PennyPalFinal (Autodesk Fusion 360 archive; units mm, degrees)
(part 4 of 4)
sketch "Sketch4" plane through (0, 0, 0) normal (0, 0, 1) x axis (1, 0, 0)
  line L1 (-27.9, 0) -> (-28, 0)
  line L2 (-27.8, -1.4) -> (-27.8, -0.1)
  line L3 (-28, -1.5) -> (-27.9, -1.5)
  line L4 (-28.1, -1.7) -> (-28.1, -1.6)
  line L5 (-27.9817, -1.8) -> (-28, -1.8)
  line L6 (-26.6181, -2.9407) -> (-27.6692, -1.9262)
  line L7 (-26.2684, -2.7223) -> (-26.4767, -2.9382)
  line L8 (-27.3, -0.9932) -> (-27.3, 0.4586)
  line L9 (-26.8722, -2.0005) -> (-26.2709, -2.5809)
  line L10 (-27.3, -1.5877) -> (-27.3, -1.5)
  line L11 (-29, 0) -> (-28, 0)
  line L12 (-29, 1.2) -> (-29, 0)
  line L13 (-28.0414, 1.2) -> (-29, 1.2)
  line L14 (-27.3293, 0.5293) -> (-27.9707, 1.1707)
  arc A1 centre (-26.5487, -2.8687) radius 0.1 clockwise from (-26.4767, -2.9382) to (-26.6181, -2.9407)
  arc A2 centre (-26.3403, -2.6528) radius 0.1 clockwise from (-26.2709, -2.5809) to (-26.2684, -2.7223)
  arc A3 centre (-28, -1.7) radius 0.1 clockwise from (-28, -1.8) to (-28.1, -1.7)
  arc A4 centre (-28, -1.6) radius 0.1 clockwise from (-28.1, -1.6) to (-28, -1.5)
  arc A5 centre (-27.9, -1.4) radius 0.1 clockwise from (-27.8, -1.4) to (-27.9, -1.5)
  arc A6 centre (-27.9, -0.1) radius 0.1 clockwise from (-27.9, 0) to (-27.8, -0.1)
  arc A7 centre (-28.0414, 1.1) radius 0.1 clockwise from (-28.0414, 1.2) to (-27.9707, 1.1707)
  arc A8 centre (-27.4, 0.4586) radius 0.1 clockwise from (-27.3293, 0.5293) to (-27.3, 0.4586)
  arc A9 centre (-25.9, -0.9932) radius 1.4 clockwise from (-26.8722, -2.0005) to (-27.3, -0.9932)
  arc A10 centre (-27.9817, -2.25) radius 0.45 clockwise from (-27.9817, -1.8) to (-27.6692, -1.9262)
  point P3 (-28, -1.5)
  point P18 (-28, -1.5)
  point P4 (-27.3, -1.5)
  point P5 (-27.3, -1.5877)
  horizontal L1
  perpendicular L1 L2
  perpendicular L2 L3
  perpendicular L4 L5
  perpendicular L6 L7
  perpendicular L7 L9
  parallel L8 L10
  parallel L1 L11
  perpendicular L11 L12
  perpendicular L12 L13
  tangent L6 A1
  tangent L7 A1
  tangent L7 A2
  tangent L9 A2
  equal A1 A2
  tangent L4 A3
  tangent L5 A3
  equal A1 A3
  tangent L4 A4
  equal A1 A4
  coincident P3 P18
  tangent L3 A5
  tangent L2 A5
  equal A1 A5
  tangent L1 A6
  tangent L2 A6
  equal A1 A6
  tangent L13 A7
  tangent L14 A7
  equal A1 A7
  tangent L14 A8
  tangent L8 A8
  equal A1 A8
  coincident P4 L8
  coincident L9 P5
  tangent L8 A9
  tangent L9 A9
  tangent L5 A10
  tangent L6 A10
  dimension "d62" radius A1 = 0.1
  dimension "d63" radius A9 = 1.4
  dimension "d64" radius A10 = 0.45
sweep "Sweep1" sketch "Sketch4" TwistAngle 0 TaperAngle 0
combine "Combine1"
extrude "Extrude14" new body sketch "Sketch3" profile of A4 L11 L12 A3 along normal blind 8
move "Move3"
combine "Combine2"
fillet "Fillet7" radius 9
component_from_bodies "Body->Comp1"
component_from_bodies "Body->Comp2"
extrude "Extrude2" add of existing geometry blind 4
extrude "Extrude3" cut of existing geometry blind -4
move "Move4"
extrude "Extrude4" add sketch "Sketch2" profile of C2 along normal blind 5
extrude "Extrude5" cut sketch "Sketch2" profile of C2 along normal blind 3
extrude "Extrude6" add of existing geometry blind 4
move "Move5"
extrude "Extrude16" new body sketch "Sketch3" profile of A4 L11 L12 A3 against normal blind 13
extrude "Extrude17" cut sketch "Sketch3" profile of A4 L11 L12 A3 against normal blind 5
move "Move6"
extrude "Extrude21" new body sketch "Sketch3" profile of C1 A7 L16 L17 A6 along normal blind 2
move "Move9"
component_from_bodies "Body->Comp3"
remove_body "RemoveBody4"
remove_body "RemoveBody5"
extrude "Extrude22" new body sketch "Sketch1" profile of C3 A4 L9 L8 A1 L7 L6 A3 A2 along normal blind 2
component_from_bodies "Body->Comp4"
sketch "Sketch5" plane through (0, 9, 0) normal (0, -1, 0) x axis (1, 0, 0)
  line L1 (-13.7255, 16.5488) -> (-11.1719, 13.4699)
  line L2 (0, 21.5) -> (0, 0)
  line L3 (13.7255, 16.5488) -> (11.1719, 13.4699)
  line L4 (-14.0447, 16.9336) -> (-13.7255, 16.5488)
  line L5 (14.0447, 16.9336) -> (13.7255, 16.5488)
  circle C1 centre (0, 0) radius 22
  circle C2 centre (0, 0) radius 17.5
  circle C3 centre (0, 0) radius 22
  point P1 (0, 0)
  point P2 (0, 0)
  point P3 (-13.7255, 16.5488)
  point P5 (13.7255, 16.5488)
  point P8 (0, 0)
  point P9 (-14.0447, 16.9336)
  point P10 (14.0447, 16.9336)
  coincident P1 P2
  vertical L2
  symmetric P3 L2 P5
  coincident P1 P8
  coincident C1 P9
  parallel L1 L4
  coincident C1 P10
  parallel L3 L5
  dimension "d125" diameter C1 = 44
extrude "Extrude9" cut sketch "Sketch1" profile of C2 C3 along normal blind 6
extrude "Extrude10" cut sketch "Sketch1" profile of C1 C2 along normal blind 16
extrude "Extrude12" cut sketch "Sketch5" profile of L1 L3 C1 L4 L5 C2 C3 against normal blind 8
extrude "Extrude1" cut sketch "Sketch3" profile of C3 C4 along normal blind 3
extrude "Extrude13" cut sketch "Sketch3" profile of C3 C4 along normal blind 8.78
scale "Scale1" ScaleFactor 1.01
fillet "Fillet1" radius 11
extrude "Extrude14" cut of existing geometry blind -3
fillet "Fillet3" radius 4.5
extrude "Extrude15" add of existing geometry blind 3
sketch "Sketch7" plane through (0, 12.22, 0) normal (0, -1, 0) x axis (1, 0, 0)
  line L1 (11.3086, 13.4396) -> (14.2101, 16.9379)
  line L2 (-14.1601, 16.9379) -> (-11.2586, 13.4396)
  arc A1 centre (0.025, -0.165) radius 17.675 clockwise from (11.3086, 13.4396) to (-11.2586, 13.4396)
  arc A2 centre (0.025, -0.165) radius 22.22 clockwise from (14.2101, 16.9379) to (-14.1601, 16.9379)
  circle C1 centre (0.025, -0.165) radius 19.5
  concentric A1 C1
  dimension "d166" diameter C1 = 39
extrude "Extrude21" cut sketch "Sketch7" profile of L1 A1 L2 C1 against normal blind 4
extrude "Extrude22" cut sketch "Sketch5" profile of L1 L3 C1 L4 L5 C2 C3 against normal blind 26
move "Move1"
sketch "Sketch6" plane through (0, -15.02, 0) normal (0, -1, 0) x axis (1, 0, 0)
  line L1 (-2.5, -16.94) -> (-7.55, -16.94)
  line L2 (-7.55, 16.61) -> (-2.5, 16.61)
  line L3 (-5.025, -0.165) -> (-5.025, 16.61)
  curve K1 (-7.675, -0.165) -> (-17.675, -0.165)
  curve K2 (-12.675, 10.835) -> (-12.675, -11.165)
  arc A1 centre (-7.55, -0.165) radius 16.775 clockwise from (-7.55, -16.94) to (-7.55, 16.61)
  arc A2 centre (-2.5, -0.165) radius 16.775 clockwise from (-2.5, 16.61) to (-2.5, -16.94)
  closed curve K3 centre (-12.675, -0.165)
  closed curve K4 centre (2.625, -0.165)
  point P8 (-5.025, 16.61)
  point P11 (-17.675, -0.165)
  point P12 (-7.675, -0.165)
  point P13 (-12.675, -11.165)
  point P14 (-12.675, 10.835)
  midpoint L2 P8
  coincident K3 P11
  coincident K3 P12
  coincident K3 P13
  coincident K3 P14
  symmetric L3 K3 K4
  dimension "d156" distance K3 = 10
  dimension "d157" = 22
extrude "Extrude1" cut sketch "Sketch6" profile of K3 K4 against normal blind 5
extrude "Extrude18" add of existing geometry blind 3
extrude "Extrude23" cut of existing geometry blind -3
extrude "Extrude24" cut of existing geometry blind -5
extrude "Extrude25" cut of existing geometry blind -4
extrude "Extrude23" add of existing geometry blind 6
fillet "Fillet8" radius 1.5
sketch "Sketch8" plane through (0, 23.37, 0) normal (0, 1, 0) x axis (-1, 0, 0)
  line L1 (2.5, -25.92) -> (7.55, -25.92)
  line L2 (7.55, 25.59) -> (2.5, 25.59)
  line L3 (2.5, 27.61) -> (7.55, 27.61)
  line L4 (7.55, -27.94) -> (2.5, -27.94)
  arc A1 centre (7.55, -0.165) radius 25.755 clockwise from (7.55, 25.59) to (7.55, -25.92)
  arc A2 centre (2.5, -0.165) radius 25.755 clockwise from (2.5, -25.92) to (2.5, 25.59)
  arc A3 centre (7.55, -0.165) radius 27.775 clockwise from (7.55, 27.61) to (7.55, -27.94)
  arc A4 centre (2.5, -0.165) radius 27.775 clockwise from (2.5, -27.94) to (2.5, 27.61)
extrude "Extrude20" cut of existing geometry blind -3
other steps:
base_feature "Base Feature1"
move "Move1"
base_feature "Base Feature1"
base_feature "Base Feature1" bodies "top"
scale "Scale1" ScaleFactor 1.01
move "Move1"
base_feature "Base Feature1" bodies "bottom"
scale "Scale1" ScaleFactor 1.01
move "Move1"
scale "Scale1" ScaleFactor 1.01
move "Move10"
create_component "CreateComponent1"
reparent_decal "ReparentDecal1"
remove_body "RemoveBody1"
create_component "CreateComponent2"
reparent_decal "ReparentDecal2"
remove_body "RemoveBody2"
create_component "CreateComponent4"
reparent_decal "ReparentDecal3"
remove_body "RemoveBody3"
create_component "CreateComponent5"
reparent_decal "ReparentDecal4"
remove_body "RemoveBody6"
named bodies: "speaker", "bottom", "top"

design "switch"
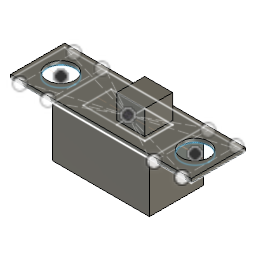
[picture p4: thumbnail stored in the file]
part number: 2026-06-04-23-07-11-302
sketch "Sketch1" plane through (0, 0, 0) normal (0, 0, 1) x axis (1, 0, 0)
  line L1 (-9.7, 2.9) -> (9.7, 2.9)
  line L2 (-9.7, -2.9) -> (-9.7, 2.9)
  line L3 (9.7, -2.9) -> (-9.7, -2.9)
  line L4 (9.7, 2.9) -> (9.7, -2.9)
  line L5 (-9.7, -2.9) -> (9.7, 2.9)
  line L6 (9.7, -2.9) -> (-9.7, 2.9)
  line L7 (-3.3, 1.5) -> (3.3, 1.5)
  line L8 (-3.3, -1.5) -> (-3.3, 1.5)
  line L9 (3.3, -1.5) -> (-3.3, -1.5)
  line L10 (3.3, 1.5) -> (3.3, -1.5)
  line L11 (-3.3, -1.5) -> (3.3, 1.5)
  line L12 (3.3, -1.5) -> (-3.3, 1.5)
  line L13 (8.7, 2.9) -> (8.7, -2.9)
  line L14 (-8.7, -2.9) -> (-8.7, 2.9)
  line L15 (5.7, 2.9) -> (5.7, -2.9)
  line L16 (-5.7, -2.9) -> (-5.7, 2.9)
  line L17 (-5.7, 0) -> (-8.7, 0)
  line L18 (3.3, 0) -> (-3.3, 0)
  line L19 (8.7, 0) -> (5.7, 0)
  line L20 (0.3, -1.5) -> (3.3, -1.5)
  line L21 (0.3, 1.5) -> (0.3, -1.5)
  line L22 (3.3, 1.5) -> (0.3, 1.5)
  line L23 (3.3, -1.5) -> (3.3, 1.5)
  line L24 (5.2, -2.9) -> (-5.2, -2.9)
  line L25 (5.2, 2.9) -> (5.2, -2.9)
  line L26 (-5.2, 2.9) -> (5.2, 2.9)
  line L27 (-5.2, -2.9) -> (-5.2, 2.9)
  line L28 (5.2, 2.9) -> (-5.2, -2.9)
  line L29 (-5.2, 2.9) -> (5.2, -2.9)
  circle C1 centre (-7.2, 0) radius 1.5
  circle C2 centre (7.2, 0) radius 1.5
  point P6 (0, 0)
  point P1 (0, 0)
  point P11 (0, 0)
  point P20 (-5.7, 0)
  point P21 (-3.3, 0)
  point P22 (-8.7, 0)
  point P23 (8.7, 0)
  point P24 (3.3, 0)
  point P25 (5.7, 0)
  point P26 (-7.2, 0)
  point P27 (7.2, 0)
  point P35 (0, 0)
  point P4 (-9.7, -2.9)
  point P5 (9.7, -2.9)
  point P3 (-9.7, 2.9)
  point P9 (-3.3, -1.5)
  point P10 (3.3, -1.5)
  point P8 (-3.3, 1.5)
  point P28 (0.3, -1.5)
  point P30 (3.3, 1.5)
  point P33 (5.2, 2.9)
  point P34 (-5.2, 2.9)
  point P32 (5.2, -2.9)
  horizontal L1
  perpendicular L1 L2
  parallel L1 L3
  parallel L2 L4
  coincident L5 P6
  coincident L6 P6
  coincident P1 P6
  horizontal L7
  perpendicular L7 L8
  parallel L7 L9
  parallel L8 L10
  coincident L11 P11
  coincident L12 P11
  coincident P6 P11
  coincident L16 P20
  coincident L8 P21
  collinear L17 L18
  coincident L14 P22
  coincident L13 P23
  coincident L10 P24
  coincident L15 P25
  collinear L18 L19
  midpoint L17 P26
  coincident P20 C1
  midpoint L19 P27
  coincident P23 C2
  horizontal L20
  vertical L21
  horizontal L22
  vertical L23
  horizontal L24
  perpendicular L24 L25
  parallel L24 L26
  parallel L25 L27
  coincident L28 P35
  coincident L29 P35
  coincident P6 P35
  dimension "d1" distance P4 P5 = 19.4
  dimension "d2" distance P3 P4 = 5.8
  dimension "d3" distance P9 P10 = 6.6
  dimension "d4" distance P8 P9 = 3
  dimension "d5" = -1
  dimension "d6" = -1
  dimension "d7" = -3
  dimension "d8" = -3
  dimension "d13" distance P10 P28 = 3
  dimension "d14" distance P10 P30 = 3
  dimension "d15" distance P33 P34 = 10.4
  dimension "d16" distance P32 P33 = 5.8
extrude "Extrude1" new body sketch "Sketch1" profile of L1 L2 L3 L4 L7 L8 L9 L10 C1 C2 along normal blind 0.4
extrude "Extrude3" add sketch "Sketch1" profile of L1 L3 L7 L8 L9 L10 L20 L21 L22 L23 L24 L25 L26 L27 against normal blind 5.4
extrude "Extrude4" add sketch "Sketch1" profile of L7 L9 L10 L20 L21 L22 L23 along normal blind 3

design "battery snap fit"
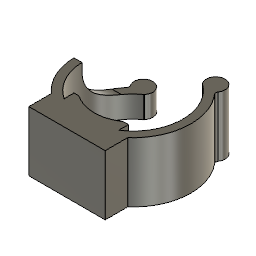
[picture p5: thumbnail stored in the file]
part number: 2026-05-30-17-13-43-080
sketch "Sketch1" plane through (0, 0, 0) normal (0, 0, 1) x axis (1, 0, 0)
  line L1 (0, 13.4605) -> (0, 0)
  line L2 (-7, -12.1) -> (7, -12.1)
  line L3 (-7, -10.1) -> (-7, -12.1)
  line L4 (7, -12.1) -> (7, -10.1)
  line L5 (-7, -10.1) -> (7, -12.1)
  line L6 (7, -10.1) -> (-7, -12.1)
  line L7 (-7, -8.6145) -> (-7, -10.1)
  line L8 (7, -8.6145) -> (7, -10.1)
  arc A1 centre (0, 0) radius 9.1 clockwise from (5.3307, 7.3752) to (-5.3668, 7.3489)
  arc A2 centre (0, 0) radius 11.1 clockwise from (-7, -8.6145) to (-8.3145, 7.3539)
  arc A3 centre (0, 0) radius 11.1 clockwise from (8.3145, 7.3539) to (7, -8.6145)
  arc A4 centre (-6.6225, 8.5293) radius 1.7322 clockwise from (-8.2261, 7.8742) to (-5.2966, 7.4146)
  arc A5 centre (6.6225, 8.5293) radius 1.7322 clockwise from (5.3307, 7.3752) to (8.2261, 7.8742)
  arc A6 centre (-8.689, 7.6851) radius 0.5 clockwise from (-8.2261, 7.8742) to (-8.3145, 7.3539)
  arc A7 centre (8.689, 7.6851) radius 0.5 clockwise from (8.3145, 7.3539) to (8.2261, 7.8742)
  arc A8 centre (-5.6028, 7.672) radius 0.4 clockwise from (-5.2966, 7.4146) to (-5.3668, 7.3489)
  point P1 (0, 0)
  point P2 (0, 0)
  point P4 (0, 0)
  point P8 (-7, -10.1)
  point P9 (7, -10.1)
  point P7 (-7, -12.1)
  coincident P1 P2
  coincident P2 P4
  vertical L1
  concentric A1 A2
  horizontal L2
  perpendicular L2 L3
  parallel L3 L4
  parallel L3 L7
  parallel L4 L8
  concentric A2 A3
  symmetric L1 A4 A5
  tangent A2 A6
  tangent A4 A6
  tangent A3 A7
  tangent A5 A7
  equal A6 A7
  tangent A1 A8
  tangent A4 A8
  dimension "d1" diameter A1 = 18.2
  dimension "d8" distance P8 P9 = 14
  dimension "d9" distance P7 P8 = 2
  dimension "d10" radius A6 = 0.5
  dimension "d11" radius A8 = 0.4
extrude "Extrude1" new body sketch "Sketch1" profile of A1 A3 L2 L3 L4 L7 L8 A4 A5 A6 A7 A8 along normal blind 10
sketch "Sketch2" plane through (0, 0, 10) normal (0, 0, 1) x axis (-1, 0, 0)
  line L1 (7, 12.1) -> (7, 8.6145)
  line L2 (-7, 12.1) -> (7, 12.1)
  line L3 (-7, 8.6145) -> (-7, 12.1)
  line L4 (7, 5.8146) -> (7, 8.6145)
  line L5 (-7, 8.6145) -> (-7, 5.8146)
  line L6 (4.0743, 5.8146) -> (7, 5.8146)
  line L7 (-7, 5.8146) -> (-4.0743, 5.8146)
  line L8 (-5, 5.8146) -> (-7, 5.8146)
  line L9 (-5, 12.1) -> (-5, 5.8146)
  line L10 (-7, 12.1) -> (-5, 12.1)
  line L11 (-7, 5.8146) -> (-7, 12.1)
  line L12 (0, -20) -> (0, -2.5)
  line L13 (5, 12.1) -> (5, 5.8146)
  arc A1 centre (-6.6225, -8.5293) radius 1.7322 clockwise from (-5.3307, -7.3752) to (-8.2261, -7.8742)
  arc A2 centre (0, 0) radius 9.1 clockwise from (-5.3307, -7.3752) to (5.3668, -7.3489)
  arc A3 centre (5.6028, -7.672) radius 0.4 clockwise from (5.2966, -7.4146) to (5.3668, -7.3489)
  arc A4 centre (6.6225, -8.5293) radius 1.7322 clockwise from (8.2261, -7.8742) to (5.2966, -7.4146)
  arc A5 centre (8.689, -7.6851) radius 0.5 clockwise from (8.2261, -7.8742) to (8.3145, -7.3539)
  arc A6 centre (0, 0) radius 11.1 clockwise from (7, 8.6145) to (8.3145, -7.3539)
  arc A7 centre (0, 0) radius 11.1 clockwise from (-8.3145, -7.3539) to (-7, 8.6145)
  arc A8 centre (-8.689, -7.6851) radius 0.5 clockwise from (-8.3145, -7.3539) to (-8.2261, -7.8742)
  arc A9 centre (0, 0) radius 7.1 clockwise from (-4.0743, 5.8146) to (4.0743, 5.8146)
  point P22 (7, 5.8146)
  point P16 (-7, 8.6145)
  point P20 (-7, 8.6145)
  point P27 (-5, 12.1)
  point P26 (-5, 5.8146)
  point P31 (5, 5.8146)
  point P32 (5, 12.1)
  point P23 (-7, 5.8146)
  vertical L4
  horizontal L6
  vertical L5
  coincident A2 P22
  coincident P16 P20
  collinear L6 L7
  concentric A2 A9
  horizontal L8
  vertical L9
  horizontal L10
  vertical L11
  coincident L2 P27
  symmetric P26 L12 P31
  symmetric P27 L12 P32
  dimension "d19" distance P23 P26 = 2
extrude "Extrude2" add sketch "Sketch2" profile of A2 L2 A9 L7 L9 L13 along normal blind 1
extrude "Extrude3" add of existing geometry blind 1
offset_faces "OffsetFaces1" distance -0.5
sketch "Sketch3" plane through (0, 0, 11) normal (0, 0, 1) x axis (-1, 0, 0)
  line L1 (-5, 5.8146) -> (-5, 7.6033)
  line L2 (-4.0743, 5.8146) -> (-5, 5.8146)
  line L3 (5, 5.8146) -> (4.0743, 5.8146)
  line L4 (5, 7.6033) -> (5, 5.8146)
  line L5 (7, 12.1) -> (7, 7.9599)
  line L6 (-7, 12.1) -> (7, 12.1)
  line L7 (-7, 7.9599) -> (-7, 12.1)
  line L8 (9.0973, 0.2232) -> (10.5976, 0.2232)
  arc A1 centre (-6.6225, -8.5293) radius 1.7322 clockwise from (-5.3307, -7.3752) to (-8.0257, -7.5135)
  arc A2 centre (0, 0) radius 9.1 clockwise from (-5.3307, -7.3752) to (-5, 7.6033)
  arc A3 centre (0, 0) radius 7.1 clockwise from (-4.0743, 5.8146) to (4.0743, 5.8146)
  arc A4 centre (0, 0) radius 9.1 clockwise from (5, 7.6033) to (5.3668, -7.3489)
  arc A5 centre (5.6028, -7.672) radius 0.4 clockwise from (5.2966, -7.4146) to (5.3668, -7.3489)
  arc A6 centre (6.6225, -8.5293) radius 1.7322 clockwise from (8.0257, -7.5135) to (5.2966, -7.4146)
  arc A7 centre (8.4307, -7.2203) radius 0.5 clockwise from (8.0257, -7.5135) to (8.051, -6.8951)
  arc A8 centre (0, 0) radius 10.6 clockwise from (7, 7.9599) to (8.051, -6.8951)
  arc A9 centre (0, 0) radius 10.6 clockwise from (-8.051, -6.8951) to (-7, 7.9599)
  arc A10 centre (-8.4307, -7.2203) radius 0.5 clockwise from (-8.051, -6.8951) to (-8.0257, -7.5135)
  point P25 (10.5976, 0.2232)
  point P26 (9.0973, 0.2232)
  coincident A8 P25
  midpoint A4 P26
  horizontal L8
extrude "Extrude4" cut sketch "Sketch3" profile of A4 A5 A6 A7 A8 L8 against normal blind 7
fillet "Fillet1" radius 5.5

design "solenoid"
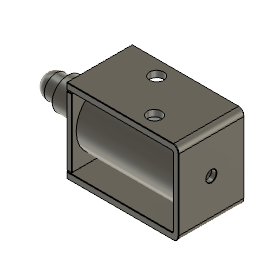
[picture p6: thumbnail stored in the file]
description: Part Number
part number: SOLENOID_01_V1_ASM
description: NOT SPECIFIED
part number: SOLENOID_CORE_01_V1
part number: SOLENOID_SHAFT_01_V1
base_feature "Base Feature"
scale "Scale1" ScaleFactor 0.3158
move "Move1"
scale "Scale2" ScaleX 0.862
scale "Scale3" ScaleY 0.8265
scale "Scale4" ScaleZ 0.666
sketch "Sketch3" plane through (-15.1623, 0, 0) normal (-1, 0, 0) x axis (0, -1, 0)
  line L1 (7.1813, -22.3363) -> (-1.066, -22.3363)
  line L2 (7.1813, -9.5495) -> (7.1813, -22.3363)
  line L3 (-1.066, -9.5495) -> (7.1813, -9.5495)
  line L4 (-1.066, -22.3363) -> (-1.066, -9.5495)
  closed curve K1 centre (4.8846, -18.5928)
  closed curve K2 centre (1.2307, -18.5928)
  closed curve K3 centre (1.2307, -11.0216)
  closed curve K4 centre (3.0577, -14.8072)
  closed curve K5 centre (4.8846, -11.0216)
  closed curve K6 centre (1.2307, -18.5928)
  closed curve K7 centre (4.8846, -18.5928)
  closed curve K8 centre (3.0577, -14.8072)
  closed curve K9 centre (4.8846, -11.0216)
  closed curve K10 centre (1.2307, -11.0216)
extrude "Extrude2" add sketch "Sketch3" profile of K1 K2 K3 K4 K5 K6 K7 K8 K9 K10 to an object
move "Move2"
scale "Scale5" ScaleX 1.0557
sketch "Sketch5" plane through (-5.0666, 0, 0) normal (-1, 0, 0) x axis (0, -1, 0)
  line L1 (7.1813, -35.1791) -> (-1.066, -35.1791)
  line L2 (7.1813, -26.5775) -> (7.1813, -35.1791)
  line L3 (-1.066, -26.5775) -> (7.1813, -26.5775)
  line L4 (-1.066, -35.1791) -> (-1.066, -26.5775)
  closed curve K1 centre (3.0577, -30.8783)
  closed curve K2 centre (3.0577, -30.8783)
  circle C1 centre (3.0577, -30.8783) radius 1.5
  circle C2 centre (3.0577, -30.8783) radius 2
  concentric K1 C1
  concentric C1 C2
  dimension "d32" diameter C1 = 3
  dimension "d33" diameter C2 = 4
extrude "Extrude4" new body sketch "Sketch5" profile of C1 along normal blind 7
extrude "Extrude3" add sketch "Sketch5" profile of K1 K2 C1 C2 along normal blind 4
fillet "Fillet3" radius 1.5
sketch "Sketch6" plane through (0, 0, -25.5704) normal (0, 0, 1) x axis (-1, 0, 0)
  line L1 (5.0222, 7.1813) -> (5.0222, -1.066)
  line L2 (-8.4768, 7.1813) -> (5.0222, 7.1813)
  line L3 (-8.4768, -1.066) -> (-8.4768, 7.1813)
  line L4 (5.0222, -1.066) -> (-8.4768, -1.066)
  line L5 (-8.4768, -1.066) -> (-9.1429, -1.066)
  line L6 (-8.4768, 7.1813) -> (-8.4768, -1.066)
  line L7 (-9.1429, 7.1813) -> (-8.4768, 7.1813)
  line L8 (-9.1429, -1.066) -> (-9.1429, 7.1813)
  line L9 (5.0222, -0.066) -> (-8.4768, -0.066)
  line L10 (-8.4768, 6.1813) -> (5.0222, 6.1813)
  line L11 (0.0222, 1.734) -> (0.0222, -0.066)
  line L12 (-4.1429, 4.3813) -> (-4.1429, 6.1813)
  circle C1 centre (0.0222, 0.834) radius 0.9
  circle C2 centre (-4.1429, 5.2813) radius 0.9
  point P15 (0.0222, -0.066)
  point P16 (0.0222, 0.834)
  point P14 (0.0222, 1.734)
  point P18 (-4.1429, 6.1813)
  point P19 (-4.1429, 5.2813)
  point P17 (-4.1429, 4.3813)
  coincident L9 P15
  midpoint L11 P16
  coincident P14 C1
  coincident L10 P18
  midpoint L12 P19
  coincident P17 C2
  dimension "d40" = -1
  dimension "d41" = -1
extrude "Extrude4" cut sketch "Sketch6" profile of C1 C2 against normal blind 1
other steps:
create_component "CreateComponent1"
create_component "CreateComponent2"

design "mainPCB"
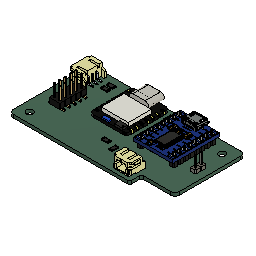
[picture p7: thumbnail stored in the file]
description: KiCad electronic assembly
part number: mainPCB 1
description: Part Number
part number: S2B-PH-SM4-TB
part number: PinHeader_2x05_P2.54mm_Vertical_SMD
part number: SoC_nRF_Sense
part number: Mic_nRF_Sense
part number: Antenna_nRF_Sense
part number: Board
part number: USB
part number: Contact
part number: Body007
base_feature "Base Feature1"
base_feature "Base Feature1"
base_feature "Base Feature1"
base_feature "Base Feature1"
base_feature "Base Feature1"
base_feature "Base Feature1"
base_feature "Base Feature1"
base_feature "Base Feature1"
base_feature "Base Feature1"
base_feature "Base Feature1"
base_feature "Base Feature1"
base_feature "Base Feature1"
base_feature "Base Feature1"
base_feature "Base Feature1"
base_feature "Base Feature1"
base_feature "Base Feature1"
base_feature "Base Feature1"
base_feature "Base Feature1"
base_feature "Base Feature1"
base_feature "Base Feature1"
base_feature "Base Feature1"
base_feature "Base Feature1"
base_feature "Base Feature1"
base_feature "Base Feature1"
base_feature "Base Feature1"
base_feature "Base Feature1"
base_feature "Base Feature1"
base_feature "Base Feature1"
base_feature "Base Feature1"
base_feature "Base Feature1"
base_feature "Base Feature1"
base_feature "Base Feature1"
base_feature "Base Feature1"
base_feature "Base Feature1"
base_feature "Base Feature1"
base_feature "Base Feature1"
base_feature "Base Feature1"
base_feature "Base Feature1"
base_feature "Base Feature1"
base_feature "Base Feature1"
base_feature "Base Feature1"
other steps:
create_component "CreateComponent1"
create_component "CreateComponent2"
create_component "CreateComponent3"
create_component "CreateComponent1"
create_component "CreateComponent2"
create_component "CreateComponent3"
create_component "CreateComponent4"
create_component "CreateComponent1"
create_component "CreateComponent2"
create_component "CreateComponent3"
create_component "CreateComponent4"
create_component "CreateComponent1"
create_component "CreateComponent2"
create_component "CreateComponent3"
create_component "CreateComponent4"
create_component "CreateComponent5"
create_component "CreateComponent6"
create_component "CreateComponent7"
create_component "CreateComponent8"
create_component "CreateComponent9"
create_component "CreateComponent10"
create_component "CreateComponent11"
create_component "CreateComponent12"
create_component "CreateComponent13"
create_component "CreateComponent4"
create_component "CreateComponent1"
create_component "CreateComponent2"
create_component "CreateComponent3"
create_component "CreateComponent4"
create_component "CreateComponent5"
create_component "CreateComponent1"
create_component "CreateComponent2"
create_component "CreateComponent3"
create_component "CreateComponent6"
create_component "CreateComponent1"
create_component "CreateComponent2"
create_component "CreateComponent3"
create_component "CreateComponent4"
create_component "CreateComponent5"
create_component "CreateComponent6"
create_component "CreateComponent7"
create_component "CreateComponent8"
create_component "CreateComponent9"
create_component "CreateComponent7"
create_component "CreateComponent8"
create_component "CreateComponent1"
create_component "CreateComponent2"
create_component "CreateComponent9"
